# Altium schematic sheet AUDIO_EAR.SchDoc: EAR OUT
size A4; Author: Silvio Navaretti; CompanyName: Arduino SRL; DrawnBy: Silvio Navaretti; Engineer: Silvio Navaretti; Organization: Arduino SRL; DocumentNumber: ASX00083; SheetNumber: 9; SheetTotal: 11; RevAuthor: Silvio Navaretti
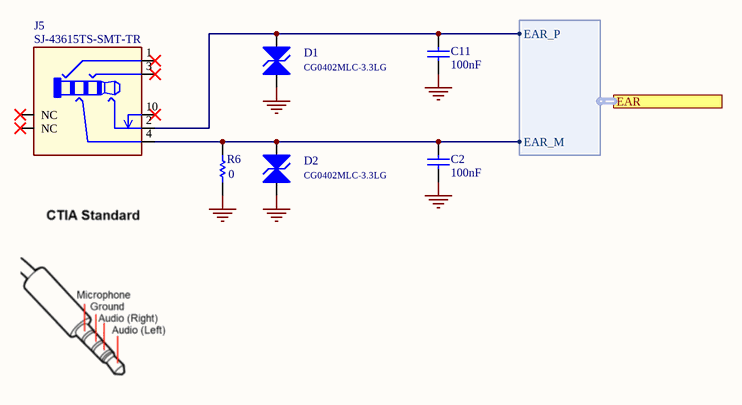
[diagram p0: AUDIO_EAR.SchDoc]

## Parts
C2  value 100nF  [CAP-0402]  (hidden comment: GRM155R61H104KE19D)
C11  value 100nF  [CAP-0402]  (hidden comment: GRM155R61H104KE19D)
D1  CG0402MLC-3.3LG  [0402]
D2  CG0402MLC-3.3LG  [0402]
J5  SJ-43615TS-SMT-TR  [SJ-43615TS-SMT-TR]
R6  value 0  [RES-0402]  (hidden comment: CRCW04020000Z0EDC)

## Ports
EAR (harness EAR)

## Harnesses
EAR: EAR_P, EAR_M

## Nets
GND: C2.1 C11.1 D1.A D2.A R6.1
NetC2_2: C2.2 D2.C J5.4 R6.2 ; port EAR.EAR_M
NetC11_2: C11.2 D1.C J5.2 ; port EAR.EAR_P

Not connected (* = marked no-connect by the designer): J5 1* 3* 10* 11(NC)* 12(NC)*

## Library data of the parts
C2 C11 = C0015-A.14: CAP CHIP 0402 100nF 10% 50V X5R; Manufacturer: Murata; Code Arduino: A5141
D1 D2 = D0073-A.3: DIODE TVS SMD 0402 3.3V ESD PROTECTION; Manufacturer: Bourns; Code Arduino: D0073; Direction: Bidirectional
J5 = J0533-A.9: CONN Audio Jack 3.5mm, 4 conductor, tip switch, SMD mid mount; Manufacturer: Same Sky; Code Arduino: J0533
R6 = R0000-A.24: RES CHIP 0402 0R 1/16W; Manufacturer: Vishay; Code Arduino: 0039; Power: 62.5mW; Tolerance: 0%; Temperature coefficient: 0ppm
